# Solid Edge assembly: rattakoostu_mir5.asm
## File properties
Author: Türk
Template: Iso Assembly.asm
Last saved by: Türk
Revision: 2
Application: Solid Edge
Username: Türk
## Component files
VlegR18_mir.par
Rehv.par
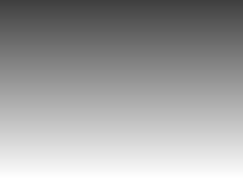
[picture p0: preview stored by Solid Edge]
